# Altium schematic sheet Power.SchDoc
size A4
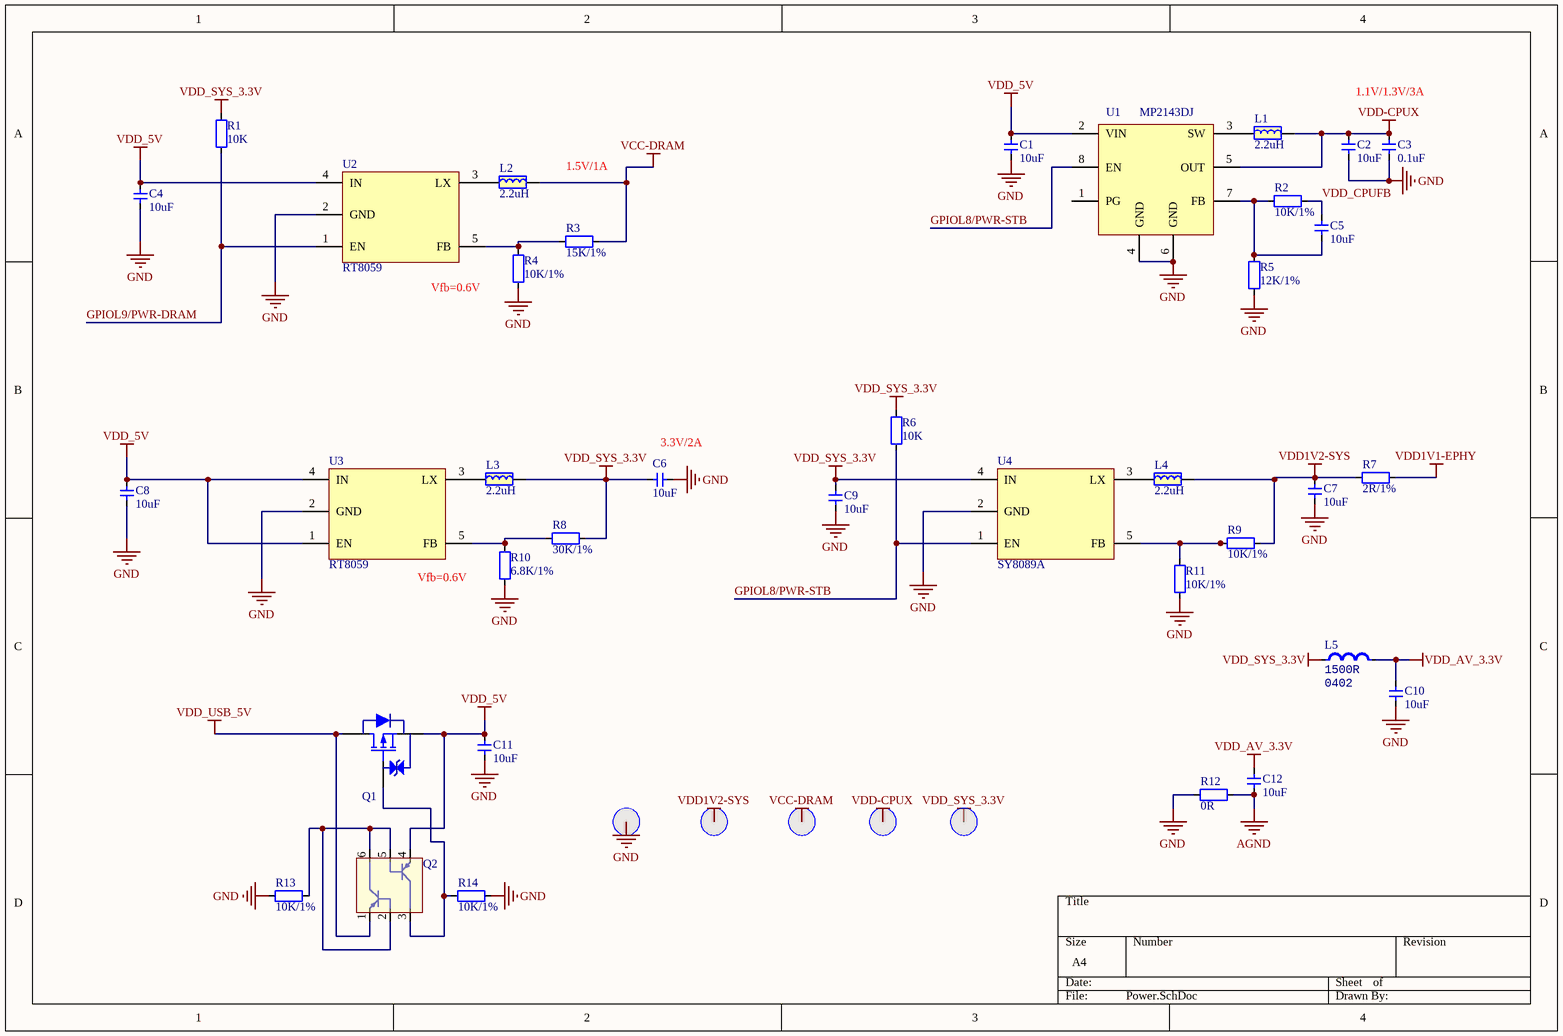
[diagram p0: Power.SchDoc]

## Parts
C1  10uF  [CAP_0402]
C2  10uF  [CAP_0402]
C3  0.1uF  [CAP_0402]
C4  10uF  [CAP_0402]
C5  10uF  [CAP_0402]
C6  10uF  [CAP_0402]
C7  10uF  [CAP_0402]
C8  10uF  [CAP_0402]
C9  10uF  [CAP_0402]
C10  10uF  [CAP_0402]
C11  10uF  [CAP_0402]
C12  10uF  [CAP_0402]
L1  2.2uH  [2520-L]
L2  2.2uH  [2520-L]
L3  2.2uH  [2520-L]
L4  2.2uH  [2520-L]
L5  value 1500R  Type: 0402  [IND_0402]  (hidden comment: H0402)
Q1  AO3415A  [SOT23-3]  (value not drawn)
Q2  BCM856BS  [SOT363-6]  (value not drawn)
R1  10K  [RES_0402]
R2  10K/1%  [RES_0402]
R3  15K/1%  [RES_0402]
R4  10K/1%  [RES_0402]
R5  12K/1%  [RES_0402]
R6  10K  [RES_0402]
R7  2R/1%  [RES_0402]
R8  30K/1%  [RES_0402]
R9  10K/1%  [RES_0402]
R10  6.8K/1%  [RES_0402]
R11  10K/1%  [RES_0402]
R12  0R  [RES_0402]
R13  10K/1%  [RES_0402]
R14  10K/1%  [RES_0402]
T1  测试点  [TEST_PT]  (value not drawn)
T2  测试点  [TEST_PT]  (value not drawn)
T3  测试点  [TEST_PT]  (value not drawn)
T4  测试点  [TEST_PT]  (value not drawn)
T5  测试点  [TEST_PT]  (value not drawn)
U1  MP2143DJ  [SOT23-8]
U2  RT8059  [SOT23-5]
U3  RT8059  [SOT23-5]
U4  SY8089A  [SOT23-5]

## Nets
AGND: C12.1 R12.1
GND: C1.1 C2.1 C3.1 C4.1 C6.1 C7.1 C8.1 C9.1 C10.1 C11.1 R4.1 R5.1 R10.1 R11.1 R12.2 R13.1 R14.2 T1.0 U1.4(GND) U1.6(GND) U2.2(GND) U3.2(GND) U4.2(GND)
VCC-DRAM: L2.2 R3.1 T3.0
VDD1V1-EPHY: R7.2
VDD1V2-SYS: C7.2 L4.2 R7.1 R9.2 T2.0
VDD-CPUX: C2.2 C3.2 L1.2 T4.0 U1.5(OUT)
VDD_5V: C1.2 C4.2 C8.2 C11.2 Q1.2(S) Q2.4 U1.2(VIN) U2.4(IN) U3.1(EN) U3.4(IN)
VDD_AV_3.3V: C10.2 C12.2 L5.2
VDD_SYS_3.3V: C6.2 C9.2 L3.2 L5.1 R1.2 R6.2 R8.1 T5.0 U4.4(IN)
VDD_USB_5V: Q1.3(D) Q2.1
GPIOL8/PWR-STB: R6.1 U1.8(EN) U4.1(EN)
GPIOL9/PWR-DRAM: R1.1 U2.1(EN)
VDD_CPUFB: C5.2 R2.2
NetC5_1: C5.1 R2.1 R5.2 U1.7(FB)
NetL1_1: L1.1 U1.3(SW)
NetL2_1: L2.1 U2.3(LX)
NetL3_1: L3.1 U3.3(LX)
NetL4_1: L4.1 U4.3(LX)
NetQ1_1: Q1.1(G) Q2.3 R14.1
NetQ2_2: Q2.2 Q2.5 Q2.6 R13.2
NetR3_2: R3.2 R4.2 U2.5(FB)
NetR8_2: R8.2 R10.2 U3.5(FB)
NetR9_1: R9.1 R11.2 U4.5(FB)

Not connected (* = marked no-connect by the designer): U1 1(PG)

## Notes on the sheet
- 1.1V/1.3V/3A
- (near L2) 1.5V/1A
- Vfb=0.6V
- (near C6) 3.3V/2A

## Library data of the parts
C1-C12 = 电容-0402: Capacitor; Value: 0.1u
L1-L4 = 电感-2520: 磁珠
L5 = Ind_0402: Inductor; Specification: ±5% 100mA
Q1 = AO3415A: MOSFET
Q2 = BCM856BS: Transistor
R1-R14 = 电阻-0402: Resistor; Value: 22R
U1 = MP2143DJ: LDO
U2 U3 = RT8059: LDO
U4 = SY8089A: LDO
